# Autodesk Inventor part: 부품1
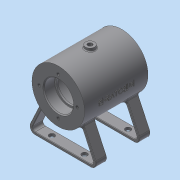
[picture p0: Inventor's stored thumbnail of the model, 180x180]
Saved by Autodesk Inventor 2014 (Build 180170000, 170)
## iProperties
Created: 2021-12
Part Number: 부품1
Material: 일반
Document SubType Name: Modeling
Designer: dg
Density: 1 g/cm^3
Appearance: 기본값
Author: dg
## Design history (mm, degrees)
sketch "스케치1"
  geometry: C1 r 29 at (0, 0); 1 further point
  constraints: 1 centre point, 1 coincident
  dimensions: "d0" = 58 diameter of C1
extrude "돌출1" new body sketch "스케치1" stored distance "d1" = 70; taper "d2" = 0 deg
node "작업 평면1"
sketch "스케치2"
  geometry: L1 (-40, -55)-(40, -55); L2 (40, -55)-(22.743, -17.993); L3 (-40, -55)-(-22.743, -17.993); L4 (20.574, -20.438)-(35.291, -52); L5 (35.291, -52)-(-35.291, -52); L6 (-35.291, -52)-(-20.574, -20.438); A1 r 29 centre (0, 0) between (-22.743, -17.993) and (22.743, -17.993) reference; 2 further points
  constraints: 12 end point, 4 point on circle, 2 horizontal, 1 equal length, 1 midpoint, 1 vertical alignment
  dimensions: "d4" = 80 distance of L1.start L1.end; "d5" = 55 distance from line of point (0, 0) L1; "d6" = 65 deg angle of L1 L2; "d7" = 65 deg angle of L1 L3; "d8" = 3 distance between parallel lines of L2 L4; "d9" = 3 distance between parallel lines of L1 L5; "d11" = 65 deg angle of L6 L5
extrude "돌출2" join sketch "스케치2" distance "d12" = 12; taper "d13" = 0 deg
node "작업 평면2"
sketch "스케치3"
  geometry: L1 (-35, 29)-(-35, -29) reference; L2 (35, -29)-(35, 29) reference; L3 (-35, 0)-(35, 0); L4 (-35, 16)-(-23, 16); L5 (-23, 16)-(-23, 14); L6 (-23, 14)-(-21, 14); L7 (-21, 14)-(-21, 21); L8 (-21, 21)-(21, 21); L9 (21, 21)-(21, 14); L10 (21, 14)-(23, 14); L11 (23, 14)-(23, 16); L12 (23, 16)-(35, 16); 1 further point
  constraints: 20 end point, 4 parallel, 4 perpendicular, 2 horizontal alignment, 2 midpoint, 2 point on line, 1 collinear, 1 vertical
  dimensions: "d14" = 12 distance of L4.start L4.end; "d15" = 2 distance of L9.end L10.end; "d16" = 42 distance of L7.end L8.end; "d17" = 28 diameter of L10 L3; "d18" = 32 diameter of L12 L3; "d19" = 42 diameter of L8 L3
revolve "회전1" sketch "스케치3" stored, may be unused: angle "d20" = 90 deg
node "작업 평면3"
sketch "스케치4"
  geometry: L1 (0, 0)-(10.945, -30.07); L2 (0, 0)-(0, -44.396)
  constraints: 4 end point, 1 vertical
  dimensions: "d21" = 20 deg angle of L2 L1; "d22" = 32 distance of L1.start L1.end
node "작업 평면4"
sketch "스케치5"
  geometry: C1 r 6 at (0, 0); 1 further point
  constraints: 1 centre point, 1 coincident
  dimensions: "d23" = 12 diameter of C1
extrude "돌출3" join sketch "스케치5" distance "d24" = 10; taper "d25" = 0 deg
node "작업 평면5"
sketch "스케치6"
  geometry: C1 r 5 at (0, 0); 1 further point
  constraints: 1 centre point, 1 coincident
  dimensions: "d27" = 10 diameter of C1
extrude "돌출4" join sketch "스케치6" distance "d28" = 10; taper "d29" = 0 deg
fillet "모깎기1" dims "d30" = 6
fillet "모깎기2" dims "d31" = 3
fillet "모깎기3" dims "d32" = 0.5
fillet "모깎기4" dims "d33" = 3
sketch "스케치7"
  geometry: L1 (61.164, 0.5)-(66.664, 0.5) reference; L2 (48.582, -5.5)-(12.582, -5.5); C1 r 3 at (48.582, -5.5); C2 r 3 at (12.582, -5.5); 3 further points
  constraints: 2 centre point, 2 end point, 1 equal radius, 1 horizontal alignment, 1 midpoint, 1 parallel, 1 vertical alignment
  dimensions: "d34" = 6 distance from line of L1 L2.start; "d35" = 36 distance of L2.end L2.start; "d36" = 6 diameter of C1
extrude "돌출5" cut sketch "스케치7" distance "d37" = 10; taper "d38" = 0 deg
sketch "스케치8"
  geometry: C1 r 16 at (0, 0) reference; 1 further point
  constraints: 1 vertical alignment
  dimensions: "d40" = 21 distance of C1.centre point (0, -21)
hole "구멍1" sketch "스케치8" at (0, -21) diameter "d41" = 3.242; stored, may be unused: countersink angle "d45" = 90 deg, drill point angle "d47" = 118 deg; dims "d42" = 8, "d43" = 4, "d44" = 2, "d46" = 10
sketch "스케치9"
  geometry: C1 r 5 at (0, 0) reference; 1 further point
  constraints: 1 coincident
hole "구멍2" sketch "스케치9" at (0, 0) diameter "d51" = 4.917; stored, may be unused: countersink angle "d55" = 90 deg, drill point angle "d57" = 118 deg; dims "d52" = 6, "d53" = 4, "d54" = 2, "d56" = 8
sketch "스케치10"
  geometry: C1 r 5 at (0, 0) reference; C2 r 1.5 at (0, 0)
  constraints: 1 centre point, 1 coincident
  dimensions: "d58" = 3 diameter of C2
extrude "돌출6" cut sketch "스케치10" distance "d59" = 30; taper "d60" = 0 deg
fillet "모깎기5" dims "d61" = 1
sketch "스케치11"
  geometry: C1 r 6 at (0, 0) reference; 1 further point
  constraints: 1 coincident
hole "구멍3" sketch "스케치11" at (0, 0) diameter "d62" = 4.917; stored, may be unused: countersink angle "d66" = 90 deg, drill point angle "d68" = 118 deg; dims "d63" = 32, "d64" = 4, "d65" = 2, "d67" = 8
fillet "모깎기6" dims "d69" = 3
fillet "모깎기7" dims "d70" = 0.3
chamfer "모따기1" distance "d71" = 1; stored, may be unused: second distance "d72" = 2, angle "d73" = 45 deg
chamfer "모따기2" distance "d74" = 1; stored, may be unused: second distance "d75" = 2, angle "d76" = 45 deg
node "작업 평면6"
sketch "스케치12"
  geometry: L1 (-35, 29)-(-35, -29) reference; L2 (-35, 29)-(35, 29) reference; 2 further points
  constraints: 1 other
  dimensions: "d78" = 35 distance from line of L1 point (0, 0); "d79" = 29 distance from line of point (0, 0) L2
feature "엠보싱1" sketch "스케치12" dims "d0" = 58, "d80" = 0.5, "d81" = 0
node "솔리드1"
mirror "대칭1"
mirror "대칭2"
pattern_circular "원형 패턴1" dims angle "d49" = 360 deg
mirror "대칭3"
node "투영된 루프1"
other parameters: "d3" = -5, "d26" = 32, "d77" = 29.5
